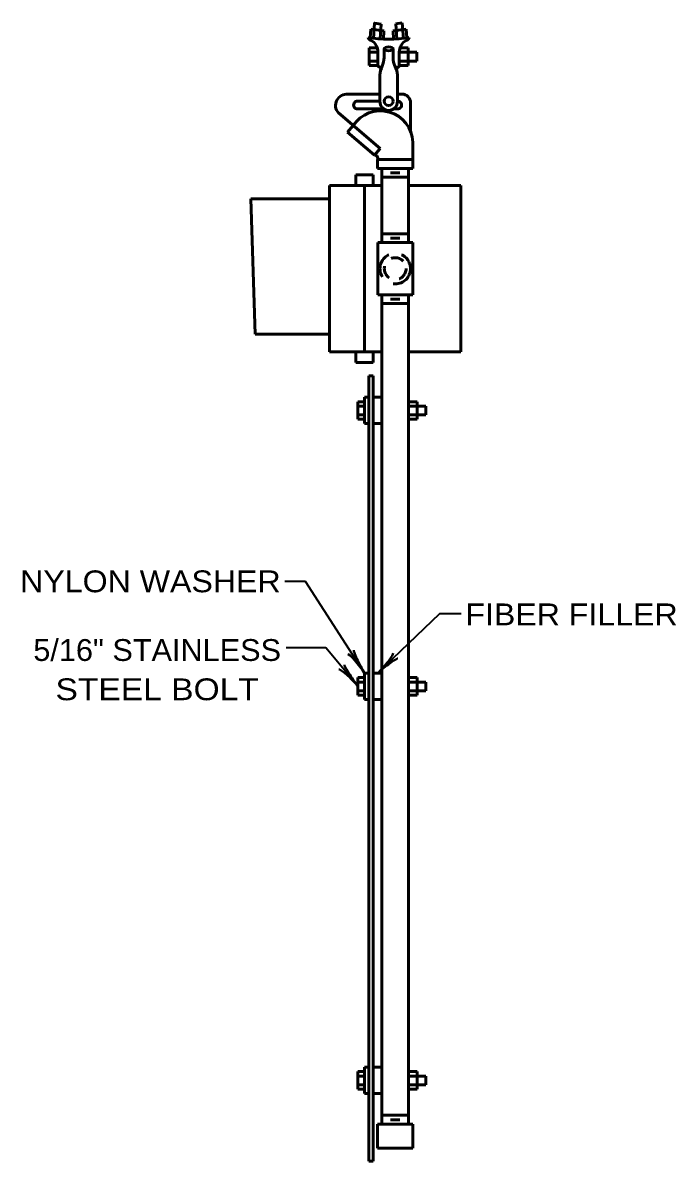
# Model space of a CAD drawing. Extents: x -1 to 679, y 1 to 441.
# Drawn here: x 214.1 to 288.9, y 193.8 to 324.2 of the extents above; entities that cross this region are included whole.
import ezdxf
from ezdxf.enums import TextEntityAlignment as Align

# ---------------------------------------------------------------- set-up
doc = ezdxf.new("R2010")
doc.units = 0
doc.linetypes.add('MEDIUM_DASHED', pattern=[4.5, 3, -1.5])
doc.linetypes.add('SHORT_DASHED', pattern=[2.7, 1.5, -1.2])
doc.layers.add('1', color=7, linetype='Continuous', lineweight=35)

msp = doc.modelspace()

# ---------------------------------------------------------------- linework, layer by layer
at = {"layer": '1', "lineweight": 53}
for p, q in [((255.019, 322.37), (255.139, 324.085)), ((257.994, 323.513), (256.508, 323.312)), ((257.555, 324.227), (256.83, 324.086)), ((256.95, 322.367), (256.83, 324.086)), ((257.712, 322.439), (257.555, 324.227)), ((258.084, 322.49), (257.994, 323.513)), ((253.891, 322.494), (253.959, 323.478)), ((253.959, 323.478), (255.46, 323.311)), ((255.393, 322.349), (255.46, 323.311)), ((256.575, 322.347), (256.508, 323.312)), ((254.707, 321.344), (253.781, 321.344)), ((253.781, 321.344), (253.781, 319.344)), ((255.502, 320.245), (255.502, 321.245)), ((256.502, 320.245), (256.502, 321.245)), ((257.298, 321.344), (258.224, 321.344)), ((258.224, 321.344), (258.224, 319.344)), ((254.781, 320.844), (253.781, 320.844)), ((254.781, 319.844), (253.781, 319.844)), ((254.781, 319.344), (254.781, 320.844)), ((257.224, 319.344), (257.224, 320.844)), ((257.224, 320.844), (259.224, 320.844)), ((257.224, 319.844), (259.224, 319.844)), ((259.224, 320.844), (259.224, 319.844)), ((254.781, 319.344), (253.781, 319.344)), ((257.224, 319.344), (258.224, 319.344)), ((255.002, 315.245), (255.002, 318.245)), ((257.002, 315.245), (257.002, 318.245)), ((255.002, 316.048), (251.355, 316.048)), ((257.522, 316.048), (257.002, 316.048)), ((255.002, 315.245), (252.46, 315.245)), ((258.522, 311.657), (258.522, 315.048)), ((255.035, 309.824), (250.25, 313.89)), ((255.446, 314.351), (252.46, 314.351)), ((257.002, 314.351), (256.558, 314.351)), ((251.952, 312.443), (251.305, 311.681)), ((254.388, 309.062), (251.305, 311.681)), ((258.772, 310.548), (258.772, 307.548)), ((255.035, 309.824), (254.388, 309.062)), ((252.227, 306.82), (252.227, 305.57)), ((252.227, 306.82), (254.227, 306.82)), ((254.227, 306.82), (254.227, 305.57)), ((258.772, 307.548), (254.727, 307.548)), ((255.227, 307.548), (255.227, 299.048)), ((258.272, 306.548), (255.227, 306.548)), ((257.272, 307.048), (256.227, 307.048)), ((258.272, 307.548), (258.272, 299.048)), ((255.227, 305.57), (249.227, 305.57)), ((253.227, 305.57), (253.227, 286.536)), ((264.272, 305.57), (258.272, 305.57)), ((264.272, 305.57), (264.272, 286.536)), ((249.227, 304.07), (240.227, 304.07)), ((240.227, 304.07), (240.727, 288.536)), ((258.272, 300.048), (255.227, 300.048)), ((258.772, 299.048), (254.773, 299.048)), ((254.773, 299.048), (254.777, 293.048)), ((257.272, 299.548), (256.227, 299.548)), ((258.772, 299.048), (258.772, 293.048)), ((258.772, 293.048), (254.777, 293.048)), ((257.272, 292.548), (256.227, 292.548)), ((258.272, 293.048), (258.272, 255.048)), ((258.272, 292.048), (255.227, 292.048)), ((249.227, 288.536), (240.727, 288.536)), ((255.227, 286.536), (249.227, 286.536)), ((252.227, 286.536), (252.227, 285.286)), ((254.227, 286.536), (254.227, 285.286)), ((264.272, 286.536), (258.272, 286.536)), ((252.227, 285.286), (254.227, 285.286)), ((253.727, 283.786), (253.727, 193.786)), ((253.727, 283.786), (254.227, 283.786)), ((254.227, 283.786), (254.227, 193.786)), ((252.477, 280.814), (253.227, 280.814)), ((252.477, 280.814), (252.477, 278.814)), ((253.227, 281.314), (253.227, 278.314)), ((253.227, 281.314), (253.727, 281.314)), ((254.227, 281.314), (255.227, 281.314)), ((259.277, 280.814), (258.277, 280.814)), ((259.277, 280.814), (259.277, 278.814)), ((252.477, 280.314), (253.227, 280.314)), ((252.477, 279.314), (253.227, 279.314)), ((260.277, 280.314), (258.277, 280.314)), ((260.277, 279.314), (258.277, 279.314)), ((260.277, 280.314), (260.277, 279.314)), ((252.477, 278.814), (253.227, 278.814)), ((253.227, 278.314), (253.727, 278.314)), ((254.227, 278.314), (255.227, 278.314)), ((259.277, 278.814), (258.277, 278.814)), ((258.272, 255.048), (258.272, 198.048)), ((252.477, 249.193), (253.227, 249.193)), ((252.477, 249.193), (252.477, 247.193)), ((253.227, 249.693), (253.227, 246.693)), ((253.227, 249.693), (253.727, 249.693)), ((254.227, 249.693), (255.227, 249.693)), ((259.277, 249.193), (258.277, 249.193)), ((259.277, 249.193), (259.277, 247.193)), ((252.477, 248.693), (253.227, 248.693)), ((260.277, 248.693), (258.277, 248.693)), ((260.277, 248.693), (260.277, 247.693)), ((252.477, 247.693), (253.227, 247.693)), ((252.477, 247.193), (253.227, 247.193)), ((253.227, 246.693), (253.727, 246.693)), ((254.227, 246.693), (255.227, 246.693)), ((260.277, 247.693), (258.277, 247.693)), ((259.277, 247.193), (258.277, 247.193)), ((252.477, 204.048), (253.227, 204.048)), ((252.477, 204.048), (252.477, 202.048)), ((252.477, 203.548), (253.227, 203.548)), ((253.227, 204.548), (253.227, 201.548)), ((253.227, 204.548), (253.727, 204.548)), ((254.227, 204.548), (255.227, 204.548)), ((259.277, 204.048), (258.277, 204.048)), ((260.277, 203.548), (258.277, 203.548)), ((259.277, 204.048), (259.277, 202.048)), ((260.277, 203.548), (260.277, 202.548)), ((252.477, 202.548), (253.227, 202.548)), ((260.277, 202.548), (258.277, 202.548)), ((252.477, 202.048), (253.227, 202.048)), ((253.227, 201.548), (253.727, 201.548)), ((254.227, 201.548), (255.227, 201.548)), ((259.277, 202.048), (258.277, 202.048)), ((258.272, 199.048), (255.227, 199.048)), ((257.272, 198.548), (256.227, 198.548)), ((254.727, 198.048), (254.727, 195.298)), ((258.772, 198.048), (254.727, 198.048)), ((258.772, 198.048), (258.772, 195.298)), ((258.772, 195.298), (254.727, 195.298)), ((253.727, 193.786), (254.227, 193.786))]:
    msp.add_line(p, q, dxfattribs=at)
at = {"layer": '1'}
for p, q in [((246.494, 260.197), (244.109, 260.211)), ((253.238, 249.693), (246.494, 260.197))]:
    msp.add_line(p, q, dxfattribs=at)
at = {"layer": '1', "lineweight": 53}
for points in [[(254.263, 322.443), (254.386, 324.2), (255.139, 324.085)], [(258.772, 308.548), (254.727, 308.548), (254.727, 307.548)], [(249.227, 305.57), (249.227, 304.07), (249.227, 288.536), (249.227, 286.536)], [(255.227, 293.048), (255.227, 255.048), (255.227, 198.048)]]:
    msp.add_lwpolyline(points, dxfattribs=at)
at = {"layer": '1'}
for points in [[(254.721, 249.693), (261.872, 256.537), (264.297, 256.537)], [(252.477, 248.209), (248.802, 252.612), (244.251, 252.612)]]:
    msp.add_lwpolyline(points, dxfattribs=at)
at = {"layer": '1', "lineweight": 53}
msp.add_circle((256.002, 315.237), 0.5, dxfattribs=at)
at = {"layer": '1', "linetype": 'MEDIUM_DASHED', "lineweight": 53}
msp.add_circle((256.755, 296.054), 1.75, dxfattribs=at)
at = {"layer": '1', "linetype": 'SHORT_DASHED', "lineweight": 53}
msp.add_circle((256.755, 296.054), 1.25, dxfattribs=at)
at = {"layer": '1', "lineweight": 53}
for centre, radius, start, end in [((254.2, 322.779), 0.611, 203.58004, 252.01356), ((256.002, 336.457), 14.121, 260.37064, 279.62936), ((253.254, 320.871), 1.528, 358.96049, 60.26465), ((258.751, 320.871), 1.528, 119.73535, 181.03951), ((257.805, 322.779), 0.611, 287.98644, 336.41996), ((249.333, 321.11), 6.229, 342.58659, 352.02537), ((258.688, 320.212), 2.186, 179.13382, 206.25421), ((255.051, 319.403), 0.276, 192.3337, 325.25389), ((257.287, 318.155), 2.287, 151.53189, 177.7435), ((256.958, 319.382), 0.268, 210.61838, 351.79404), ((254.717, 318.155), 2.287, 2.2565, 28.46811), ((251.226, 314.752), 1.302, 84.35792, 221.42863), ((257.522, 315.048), 1, 0, 90), ((252.429, 314.798), 0.448, 85.93331, 274.06669), ((256.002, 315.185), 1.002, 176.52918, 3.47082), ((257.034, 314.798), 0.448, 265.93331, 94.06669), ((255.066, 310.431), 3.707, 1.80469, 147.13236), ((254.387, 308.693), 0.369, 336.87776, 89.95193)]:
    msp.add_arc(centre, radius, start, end, dxfattribs=at)
msp.add_ellipse((256.002, 321.245), major_axis=(0.5, 0), ratio=0.434926, dxfattribs=at)
at = {"layer": '1', "lineweight": 40}
for centre, major_axis, ratio, start_param, end_param in [((252.416, 250.462), (1.096, -1.418), 0.122415, 0.8963533, 3.1415927), ((252.416, 250.462), (1.096, -1.418), 0.122415, 0.8963533, 3.1415927), ((252.811, 250.75), (-0.801, 1.573), 0.07063, 6.2823074, 8.5597026), ((252.811, 250.75), (-0.801, 1.573), 0.07063, 6.2823074, 8.5597026), ((255.318, 250.647), (-1.182, -1.348), 0.122415, 0.8963533, 3.1415927), ((255.318, 250.647), (-1.182, -1.348), 0.122415, 0.8963533, 3.1415927), ((251.921, 249.205), (-0.991, 1.461), 0.07063, 6.2823074, 8.5597026), ((255.677, 250.314), (-1.39, -1.088), 0.07063, 3.1407148, 5.41811), ((255.677, 250.314), (-1.39, -1.088), 0.07063, 3.1407148, 5.41811), ((251.566, 248.87), (1.264, -1.271), 0.122415, 0.8963533, 3.1415927)]:
    msp.add_ellipse(centre, major_axis=major_axis, ratio=ratio, start_param=start_param, end_param=end_param, dxfattribs=at)

# ---------------------------------------------------------------- texts
at = {"layer": '1', "width": 1.1}
for s, p in [('NYLON WASHER', (213.806, 258.978)), ('FIBER FILLER', (264.782, 255.192))]:
    msp.add_text(s, height=2.5, dxfattribs=at).set_placement(p)
at = {"layer": '1'}
for s, width, p in [('5/16" STAINLESS', 1.05, (229.496, 251.108)), ('STEEL BOLT', 1.15, (229.496, 246.608))]:
    msp.add_text(s, height=2.5, dxfattribs=dict(at, width=width)).set_placement(p, align=Align.CENTER)

doc.saveas('drawing.dxf')
